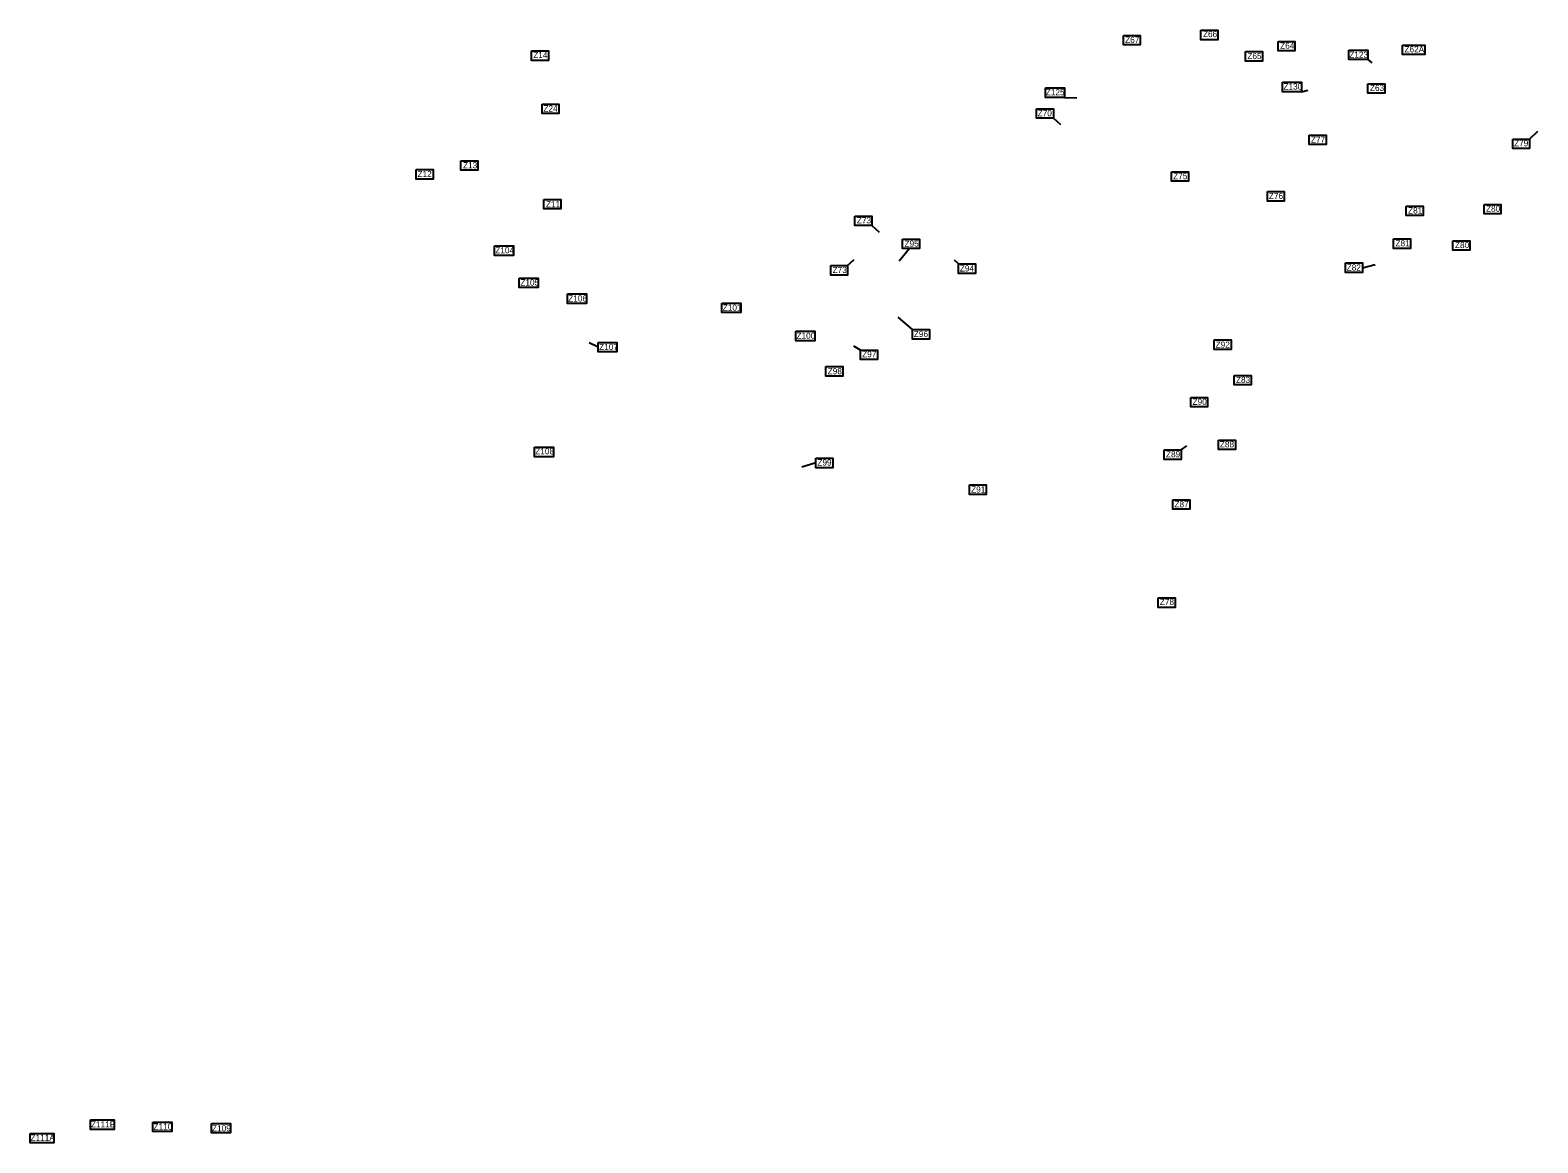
# Model space of a CAD drawing. Extents: x -443485 to -434416, y -1135265 to -1129797.
# Drawn here: x -443485 to -441040, y -1133468 to -1131664 of the extents above; entities that cross this region are included whole.
import ezdxf

# ---------------------------------------------------------------- set-up
doc = ezdxf.new("R2010")
doc.units = 0
doc.layers.add('Vrstva 3', color=7, linetype='Continuous')
doc.layers.add('Vrstva 8', color=7, linetype='Continuous')

msp = doc.modelspace()

# ---------------------------------------------------------------- linework, layer by layer
at = {"layer": 'Vrstva 3'}
for p, q in [((-441825.2, -1131807.1), (-441813.8, -1131817.4)), ((-441052.9, -1131840.8), (-441039.6, -1131827.8)), ((-442119.8, -1131981.1), (-442108.1, -1131991.8)), ((-442058.5, -1132018.5), (-442075.2, -1132039)), ((-442159, -1132046), (-442148.7, -1132036.3)), ((-441979.2, -1132043), (-441985.6, -1132037)), ((-441324.1, -1132049.4), (-441303.6, -1132044)), ((-442053.6, -1132149.7), (-442077, -1132129.5)), ((-442563.8, -1132178.3), (-442578.2, -1132171.1)), ((-442137.9, -1132182.9), (-442149.2, -1132176.8)), ((-441618.1, -1132344.9), (-441608.8, -1132338.2)), ((-442210.4, -1132366.1), (-442233.5, -1132372.9))]:
    msp.add_line(p, q, dxfattribs=at)
for points in [[(-441711.8, -1131672.7), (-441684.5, -1131672.7), (-441684.5, -1131688.1), (-441711.8, -1131688.1)], [(-441586.1, -1131664.3), (-441558.7, -1131664.3), (-441558.7, -1131679.7), (-441586.1, -1131679.7)], [(-441460.9, -1131682.5), (-441433.5, -1131682.5), (-441433.5, -1131697.9), (-441460.9, -1131697.9)], [(-442671.7, -1131697.8), (-442644.4, -1131697.8), (-442644.4, -1131713.2), (-442671.7, -1131713.2)], [(-441513.5, -1131699.1), (-441486.1, -1131699.1), (-441486.1, -1131714.5), (-441513.5, -1131714.5)], [(-441259.3, -1131688.5), (-441223.1, -1131688.5), (-441223.1, -1131703.9), (-441259.3, -1131703.9)], [(-441315.3, -1131751.1), (-441287.9, -1131751.1), (-441287.9, -1131766.5), (-441315.3, -1131766.5)], [(-442654.5, -1131784.2), (-442627.2, -1131784.2), (-442627.2, -1131799.6), (-442654.5, -1131799.6)], [(-441852.6, -1131791.7), (-441825.2, -1131791.7), (-441825.2, -1131807.1), (-441852.6, -1131807.1)], [(-441410.4, -1131834.5), (-441383, -1131834.5), (-441383, -1131849.9), (-441410.4, -1131849.9)], [(-441080.2, -1131840.8), (-441052.9, -1131840.8), (-441052.9, -1131856.2), (-441080.2, -1131856.2)], [(-442786.3, -1131876), (-442759, -1131876), (-442759, -1131891.4), (-442786.3, -1131891.4)], [(-442858.8, -1131890.4), (-442831.4, -1131890.4), (-442831.4, -1131905.8), (-442858.8, -1131905.8)], [(-441633.7, -1131893.9), (-441606.4, -1131893.9), (-441606.4, -1131909.3), (-441633.7, -1131909.3)], [(-441478.3, -1131925.9), (-441450.9, -1131925.9), (-441450.9, -1131941.3), (-441478.3, -1131941.3)], [(-442651.8, -1131938.6), (-442624.4, -1131938.6), (-442624.4, -1131954), (-442651.8, -1131954)], [(-441253, -1131949.4), (-441225.6, -1131949.4), (-441225.6, -1131964.8), (-441253, -1131964.8)], [(-441126.7, -1131946.9), (-441099.4, -1131946.9), (-441099.4, -1131962.3), (-441126.7, -1131962.3)], [(-442147.2, -1131965.7), (-442119.8, -1131965.7), (-442119.8, -1131981.1), (-442147.2, -1131981.1)], [(-441273.5, -1132002.7), (-441246.1, -1132002.7), (-441246.1, -1132018.1), (-441273.5, -1132018.1)], [(-442731.9, -1132014.2), (-442701.2, -1132014.2), (-442701.2, -1132029.6), (-442731.9, -1132029.6)], [(-442069.8, -1132003.1), (-442042.5, -1132003.1), (-442042.5, -1132018.5), (-442069.8, -1132018.5)], [(-441177.4, -1132005.6), (-441150, -1132005.6), (-441150, -1132021), (-441177.4, -1132021)], [(-442186.4, -1132046), (-442159, -1132046), (-442159, -1132061.4), (-442186.4, -1132061.4)], [(-441979.2, -1132043.3), (-441951.9, -1132043.3), (-441951.9, -1132058.7), (-441979.2, -1132058.7)], [(-441351.4, -1132041.7), (-441324.1, -1132041.7), (-441324.1, -1132057.1), (-441351.4, -1132057.1)], [(-442691.5, -1132066.2), (-442660.7, -1132066.2), (-442660.7, -1132081.6), (-442691.5, -1132081.6)], [(-442613.5, -1132092), (-442582.8, -1132092), (-442582.8, -1132107.4), (-442613.5, -1132107.4)], [(-442363, -1132106.9), (-442332.2, -1132106.9), (-442332.2, -1132122.3), (-442363, -1132122.3)], [(-442563.8, -1132170.6), (-442533.1, -1132170.6), (-442533.1, -1132186), (-442563.8, -1132186)], [(-442242.9, -1132152.5), (-442212.2, -1132152.5), (-442212.2, -1132167.9), (-442242.9, -1132167.9)], [(-442053.6, -1132149.7), (-442026.2, -1132149.7), (-442026.2, -1132165.1), (-442053.6, -1132165.1)], [(-441564.6, -1132166.6), (-441537.2, -1132166.6), (-441537.2, -1132182), (-441564.6, -1132182)], [(-442137.9, -1132182.9), (-442110.5, -1132182.9), (-442110.5, -1132198.2), (-442137.9, -1132198.2)], [(-442194.3, -1132209.9), (-442166.9, -1132209.9), (-442166.9, -1132225.3), (-442194.3, -1132225.3)], [(-441532.1, -1132224.2), (-441504.8, -1132224.2), (-441504.8, -1132239.6), (-441532.1, -1132239.6)], [(-441602.6, -1132259.7), (-441575.2, -1132259.7), (-441575.2, -1132275.1), (-441602.6, -1132275.1)], [(-442667.1, -1132340.5), (-442636.3, -1132340.5), (-442636.3, -1132355.9), (-442667.1, -1132355.9)], [(-441645.5, -1132344.9), (-441618.1, -1132344.9), (-441618.1, -1132360.3), (-441645.5, -1132360.3)], [(-441557.5, -1132329), (-441530.2, -1132329), (-441530.2, -1132344.4), (-441557.5, -1132344.4)], [(-442210.4, -1132358.4), (-442183, -1132358.4), (-442183, -1132373.8), (-442210.4, -1132373.8)], [(-441961.6, -1132401.7), (-441934.2, -1132401.7), (-441934.2, -1132417.1), (-441961.6, -1132417.1)], [(-441631.5, -1132425.8), (-441604.1, -1132425.8), (-441604.1, -1132441.2), (-441631.5, -1132441.2)], [(-441655.3, -1132585), (-441627.9, -1132585), (-441627.9, -1132600.4), (-441655.3, -1132600.4)], [(-443387, -1133431.3), (-443348.5, -1133431.3), (-443348.5, -1133446.7), (-443387, -1133446.7)], [(-443286.1, -1133434.8), (-443255.3, -1133434.8), (-443255.3, -1133450.2), (-443286.1, -1133450.2)], [(-443190.7, -1133437.1), (-443160, -1133437.1), (-443160, -1133452.5), (-443190.7, -1133452.5)], [(-443484.9, -1133453.1), (-443446.5, -1133453.1), (-443446.5, -1133468.5), (-443484.9, -1133468.5)]]:
    msp.add_lwpolyline(points, close=True, dxfattribs=at)
at = {"layer": 'Vrstva 8'}
for p, q in [((-441315.6, -1131712), (-441308.9, -1131717.3)), ((-441807.3, -1131773.2), (-441787.3, -1131774.2)), ((-441422.7, -1131764.2), (-441412.4, -1131761.3))]:
    msp.add_line(p, q, dxfattribs=at)
for points in [[(-441346.4, -1131696.6), (-441315.6, -1131696.6), (-441315.6, -1131712), (-441346.4, -1131712)], [(-441838.1, -1131757.8), (-441807.3, -1131757.8), (-441807.3, -1131773.2), (-441838.1, -1131773.2)], [(-441453.5, -1131748.8), (-441422.7, -1131748.8), (-441422.7, -1131764.2), (-441453.5, -1131764.2)]]:
    msp.add_lwpolyline(points, close=True, dxfattribs=at)

# ---------------------------------------------------------------- texts
at = {"layer": 'Vrstva 3'}
for s, p in [('Z67', (-441708.9, -1131685)), ('Z66', (-441582.7, -1131675.6)), ('Z64', (-441457.5, -1131694.4)), ('Z14', (-442668.9, -1131709.6)), ('Z65', (-441510.7, -1131711.2)), ('Z62A', (-441255.9, -1131700.3)), ('Z63', (-441311.9, -1131762.9)), ('Z24', (-442652.4, -1131796.3)), ('Z70', (-441850.8, -1131803.9)), ('Z77', (-441407.6, -1131846.7)), ('Z79', (-441078.1, -1131852.6)), ('Z13', (-442782.8, -1131888.3)), ('Z12', (-442856.6, -1131902.5)), ('Z75', (-441631, -1131906)), ('Z76', (-441475.8, -1131938.1)), ('Z11', (-442648.3, -1131951.5)), ('Z81', (-441250.1, -1131961.6)), ('Z80', (-441123.6, -1131958.7)), ('Z73', (-442144, -1131977.5)), ('Z104', (-442730.5, -1132026.2)), ('Z95', (-442066.8, -1132015.4)), ('Z81', (-441270.5, -1132014.9)), ('Z80', (-441174, -1132017.7)), ('Z73', (-442183.4, -1132058.1)), ('Z94', (-441977.1, -1132055.6)), ('Z82', (-441349.6, -1132054)), ('Z105', (-442689.8, -1132078.4)), ('Z106', (-442612.2, -1132104.3)), ('Z101', (-442361.6, -1132119.1)), ('Z107', (-442562, -1132182.9)), ('Z100', (-442242, -1132164.7)), ('Z96', (-442051.7, -1132161.9)), ('Z92', (-441562.2, -1132179.2)), ('Z97', (-442135.5, -1132194.7)), ('Z98', (-442191.4, -1132222.2)), ('Z83', (-441529.2, -1132236.4)), ('Z90', (-441599.6, -1132271.8)), ('Z108', (-442665.7, -1132352)), ('Z88', (-441555.3, -1132340.8)), ('Z99', (-442208.1, -1132370.3)), ('Z89', (-441642.7, -1132357)), ('Z91', (-441958.8, -1132414.1)), ('Z87', (-441629, -1132437.9)), ('Z78', (-441652.7, -1132596.4)), ('Z111B', (-443386.3, -1133443.6)), ('Z110', (-443284.8, -1133447.1)), ('Z109', (-443189.9, -1133449.9)), ('Z111A', (-443484.3, -1133465.4))]:
    msp.add_text(s, height=10, dxfattribs=at).set_placement(p)
at = {"layer": 'Vrstva 8'}
for s, p in [('Z123', (-441345.4, -1131709.1)), ('Z130', (-441452.2, -1131760.6)), ('Z125', (-441837.7, -1131769.9))]:
    msp.add_text(s, height=10, dxfattribs=at).set_placement(p)

doc.saveas('drawing.dxf')
